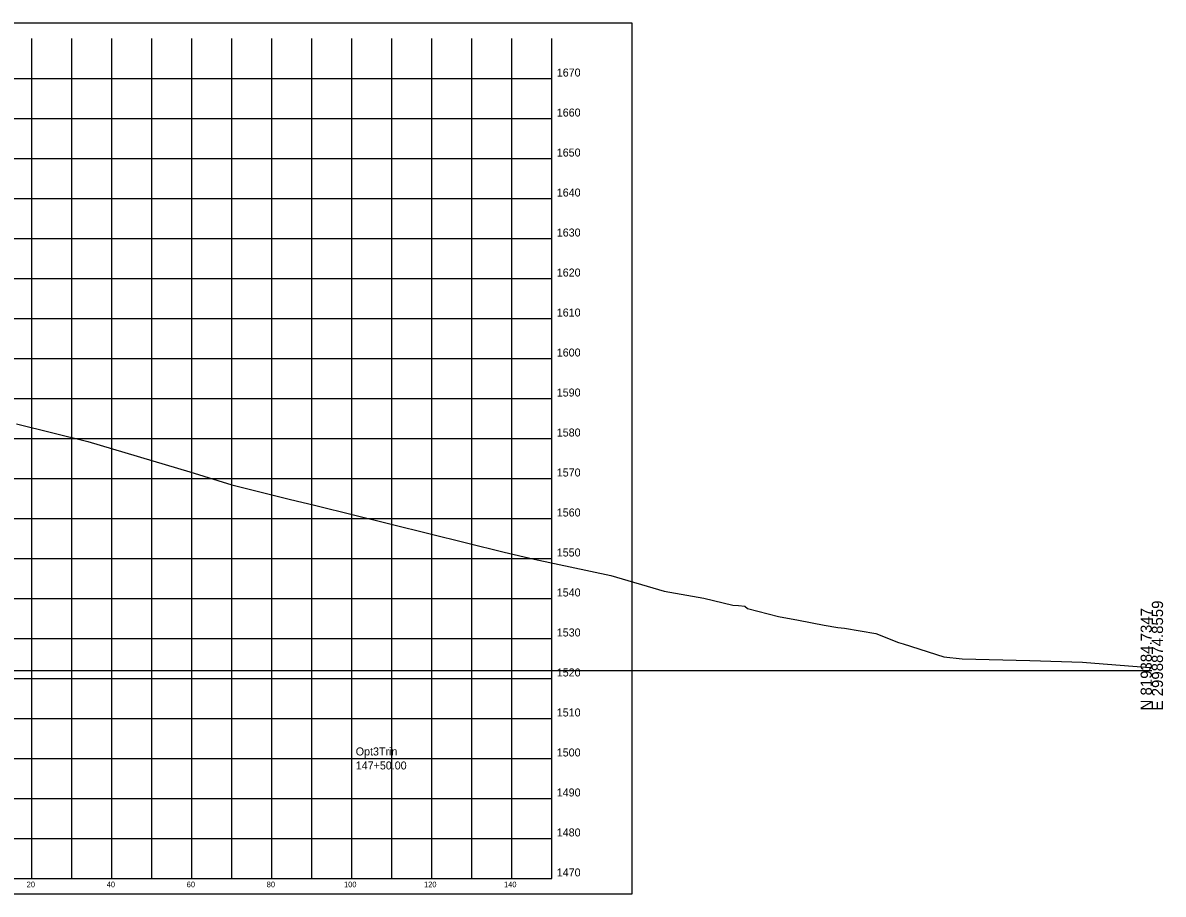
# Model space of a CAD drawing. Extents: x -26 to 603, y -10 to 4805.
# Drawn here: x 317.8 to 602.8, y 1944.1 to 2161.9 of the extents above; entities that cross this region are included whole.
import ezdxf

# ---------------------------------------------------------------- set-up
doc = ezdxf.new("R2010")
doc.units = 0
for name, color, linetype in [('DESIGN - SHEET - Corner Text', 7, 'Continuous'), ('DESIGN - SHEET - Light Grid', 7, 'Continuous'), ('DESIGN - SHEET - Linework', 7, 'Continuous'), ('DESIGN - SHEET - Plot Shape', 7, 'Continuous'), ('DESIGN - TYPICAL - Warning Text', 7, 'Continuous'), ('SURVEY - GROUND - Top of Ground', 7, 'Continuous')]:
    doc.layers.add(name, color=color, linetype=linetype)

msp = doc.modelspace()

# ---------------------------------------------------------------- linework, layer by layer
at = {"layer": 'DESIGN - SHEET - Light Grid'}
msp.add_line((300, 2000), (600, 2000), dxfattribs=at)
at = {"layer": 'DESIGN - SHEET - Linework'}
for p, q in [((320, 1948), (320, 2158)), ((330, 1948), (330, 2158)), ((340, 1948), (340, 2158)), ((350, 1948), (350, 2158)), ((360, 1948), (360, 2158)), ((370, 1948), (370, 2158)), ((380, 1948), (380, 2158)), ((390, 1948), (390, 2158)), ((400, 1948), (400, 2158)), ((410, 1948), (410, 2158)), ((420, 1948), (420, 2158)), ((430, 1948), (430, 2158)), ((440, 1948), (440, 2158)), ((150, 2148), (450, 2148)), ((150, 2138), (450, 2138)), ((150, 2128), (450, 2128)), ((150, 2118), (450, 2118)), ((150, 2108), (450, 2108)), ((150, 2098), (450, 2098)), ((150, 2088), (450, 2088)), ((150, 2078), (450, 2078)), ((150, 2068), (450, 2068)), ((150, 2058), (450, 2058)), ((150, 2048), (450, 2048)), ((150, 2038), (450, 2038)), ((150, 2028), (450, 2028)), ((150, 2018), (450, 2018)), ((150, 2008), (450, 2008)), ((150, 1998), (450, 1998)), ((150, 1988), (450, 1988)), ((150, 1978), (450, 1978)), ((150, 1968), (450, 1968)), ((150, 1958), (450, 1958))]:
    msp.add_line(p, q, dxfattribs=at)
msp.add_lwpolyline([(150, 2158), (150, 1948), (450, 1948), (450, 2158)], dxfattribs=at)
at = {"layer": 'DESIGN - SHEET - Plot Shape'}
msp.add_lwpolyline([(130, 2161.94), (470, 2161.94), (470, 1944.06), (130, 1944.06)], close=True, dxfattribs=at)
at = {"layer": 'SURVEY - GROUND - Top of Ground'}
msp.add_line((391, 2041.22), (438.12, 2029.56), dxfattribs=at)
for points in [[(316.17, 2061.63), (334.05, 2057.23), (359.54, 2049.63), (370.06, 2046.43), (384.35, 2042.86), (391, 2041.22)], [(438.12, 2029.56), (445.61, 2027.82), (464.79, 2023.73), (478.06, 2019.84), (487.97, 2018.07), (495.28, 2016.32), (496.68, 2016.27), (498.28, 2016.09), (498.89, 2015.47), (506.7, 2013.52), (511.67, 2012.57), (518.11, 2011.33), (521.51, 2010.78), (523.18, 2010.58), (531.01, 2009.25), (536.69, 2006.99), (537.84, 2006.64), (547.97, 2003.42), (552.62, 2002.93), (569.53, 2002.49), (582.71, 2002.09), (585.75, 2001.84), (598.43, 2000.83), (600, 2000.74)]]:
    msp.add_lwpolyline(points, dxfattribs=at)

# ---------------------------------------------------------------- texts
at = {"layer": 'DESIGN - SHEET - Corner Text'}
for s, height, p in [('1670', 2, (451.25, 2148.5)), ('1660', 2, (451.25, 2138.5)), ('1650', 2, (451.25, 2128.5)), ('1640', 2, (451.25, 2118.5)), ('1630', 2, (451.25, 2108.5)), ('1620', 2, (451.25, 2098.5)), ('1610', 2, (451.25, 2088.5)), ('1600', 2, (451.25, 2078.5)), ('1590', 2, (451.25, 2068.5)), ('1580', 2, (451.25, 2058.5)), ('1570', 2, (451.25, 2048.5)), ('1560', 2, (451.25, 2038.5)), ('1550', 2, (451.25, 2028.5)), ('1540', 2, (451.25, 2018.5)), ('1530', 2, (451.25, 2008.5)), ('1520', 2, (451.25, 1998.5)), ('1510', 2, (451.25, 1988.5)), ('1500', 2, (451.25, 1978.5)), ('1490', 2, (451.25, 1968.5)), ('1480', 2, (451.25, 1958.5)), ('1470', 2, (451.25, 1948.5)), ('20', 1.4, (318.74, 1945.8)), ('40', 1.4, (338.74, 1945.8)), ('60', 1.4, (358.74, 1945.8)), ('80', 1.4, (378.74, 1945.8)), ('100', 1.4, (398.06, 1945.8)), ('120', 1.4, (418.06, 1945.8)), ('140', 1.4, (438.06, 1945.8))]:
    msp.add_text(s, height=height, dxfattribs=at).set_placement(p)
at = {"layer": 'DESIGN - SHEET - Light Grid'}
for s, p in [('E 2998874.8559', (602.8, 1990)), ('N 819384.7347', (600, 1990))]:
    msp.add_text(s, height=2.8, rotation=90, dxfattribs=at).set_placement(p)
at = {"layer": 'DESIGN - TYPICAL - Warning Text'}
for s, p in [('Opt3Trin', (401, 1978.75)), ('147+50.00', (401, 1975.25))]:
    msp.add_text(s, height=2, dxfattribs=at).set_placement(p)

doc.saveas('drawing.dxf')
